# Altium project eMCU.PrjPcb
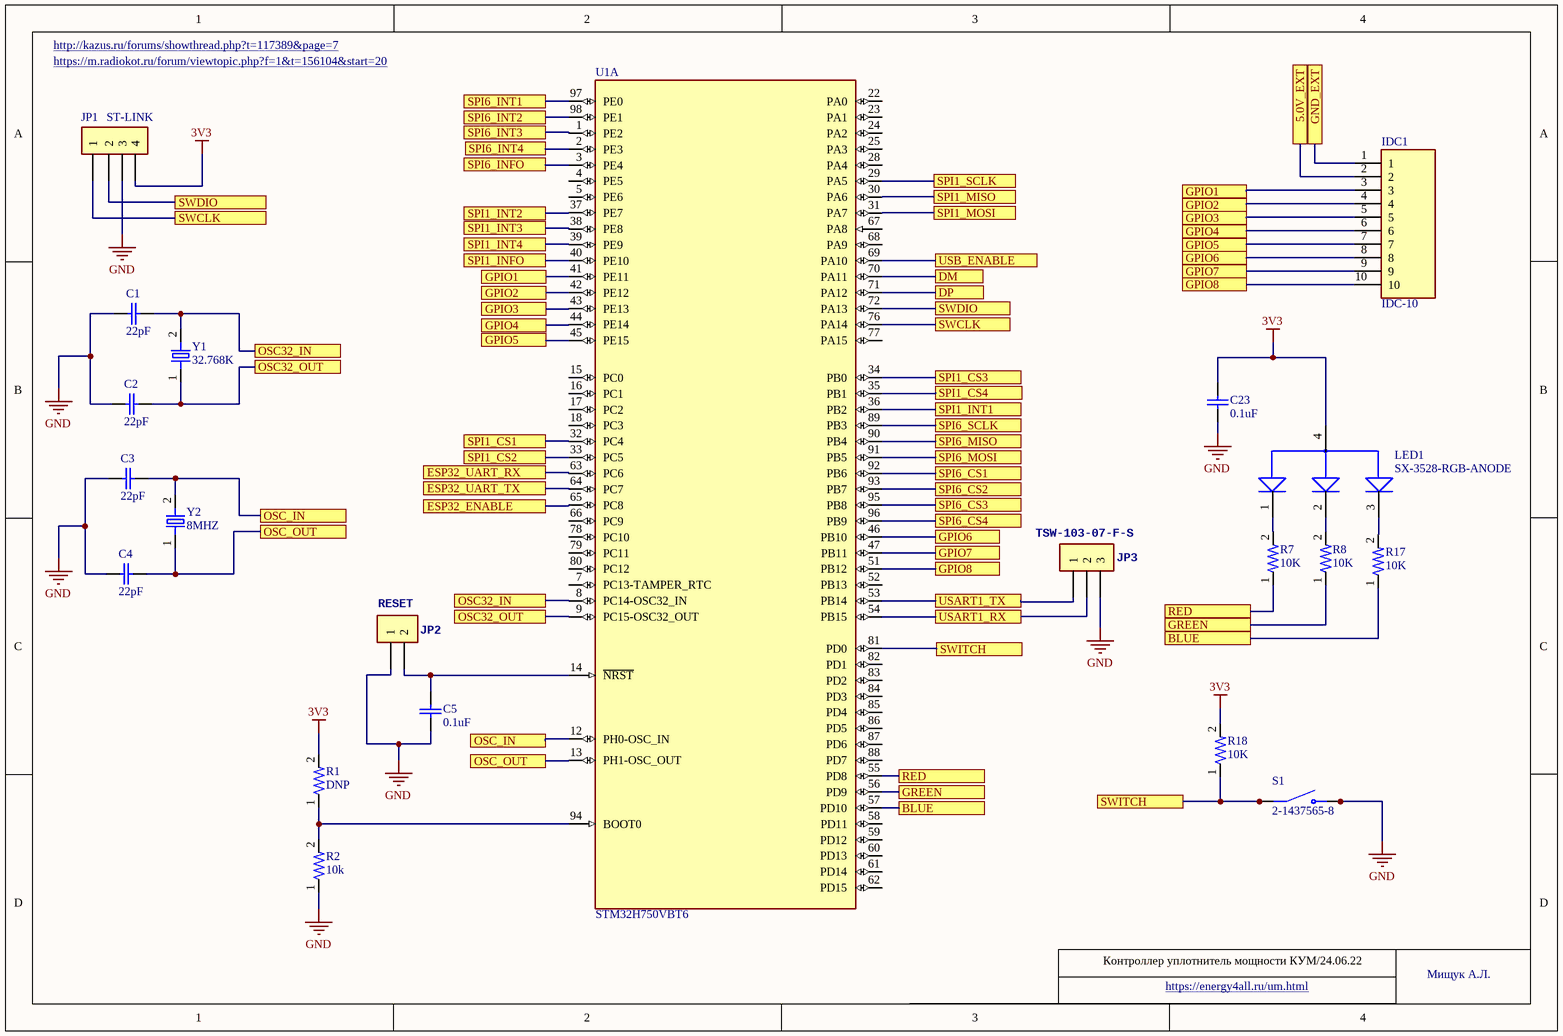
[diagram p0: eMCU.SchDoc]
5 sheets, 66 parts. Net scope: flat (ports and power ports of the same name join across sheets).
Board file: eMCU.PcbDoc
Sheets:
  eMCU.SchDoc
  eSupply.SchDoc
  eUSB.SchDoc
  eWiFi.SchDoc
  eConnect.SchDoc

## Sheet eMCU.SchDoc
size A4; SheetNumber: 1; SheetTotal: 6

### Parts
C1  22pF  [CAP_0603]
C2  22pF  [CAP_0603]
C3  22pF  [CAP_0603]
C4  22pF  [CAP_0603]
C5  0.1uF  [CAP_0603]
C23  0.1uF  [CAP_0603]
IDC1  IDC-10  [IDC-10]
JP1  ST-LINK  [TSW-104-07-F-S]
JP2  RESET  [TSW-102-07-F-S]
JP3  TSW-103-07-F-S  [TSW-103-07-F-S]
LED1  SX-3528-RGB-ANODE  [SX-3528-RGB-ANODE]
R1  DNP  [RESC1608X50N]
R2  10k  [RESC1608X50N]
R7  10K  [RESC1608X50N]
R8  10K  [RESC1608X50N]
R17  10K  [RESC1608X50N]
R18  10K  [RESC1608X50N]
S1  2-1437565-8  [2-1437565-8]
U1  STM32H750VBT6  [STM32H750VBT6]  (part A of 5)
Y1  32.768K  [NX3215SA]
Y2  8MHZ  [NX3225GD]

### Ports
5.0V_EXT, BLUE, DM, DP, ESP32_ENABLE, ESP32_UART_RX, ESP32_UART_TX, GND_EXT, GPIO1, GPIO2, GPIO3, GPIO4, GPIO5, GPIO6, GPIO7, GPIO8, GREEN, OSC32_IN, OSC32_OUT, OSC_IN, OSC_OUT, RED, SPI1_CS1, SPI1_CS2, SPI1_CS3, SPI1_CS4, SPI1_INFO, SPI1_INT1, SPI1_INT2, SPI1_INT3, SPI1_INT4, SPI1_MISO, SPI1_MOSI, SPI1_SCLK, SPI6_CS1, SPI6_CS2, SPI6_CS3, SPI6_CS4, SPI6_INFO, SPI6_INT1, SPI6_INT2, SPI6_INT3, SPI6_INT4, SPI6_MISO, SPI6_MOSI, SPI6_SCLK, SWCLK, SWDIO, SWITCH, USART1_RX, USART1_TX, USB_ENABLE

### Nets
3V3: C23.2 JP1.4 LED1.4(ANODE) R1.2 R18.2
GND: C1.1 C2.1 C3.1 C4.1 C5.1 C23.1 JP1.3 JP2.1 JP3.3 R2.1 S1.3(NO) S1.4(NO)
NetC1_2: C1.2 U1.8(PC14-OSC32_IN) Y1.2 ; port OSC32_IN
NetC2_2: C2.2 U1.9(PC15-OSC32_OUT) Y1.1 ; port OSC32_OUT
NetC3_2: C3.2 U1.12(PH0-OSC_IN) Y2.2 ; port OSC_IN
NetC4_2: C4.2 U1.13(PH1-OSC_OUT) Y2.1 ; port OSC_OUT
NetC5_2: C5.2 JP2.2 U1.14(~{NRST})
NetC21_2: U1.65(PC8) ; port ESP32_ENABLE
NetIDC1_1: IDC1.1 ; port GND_EXT
NetIDC1_2: IDC1.2 ; port 5.0V_EXT
NetIDC1_3: IDC1.3 U1.41(PE11) ; port GPIO1
NetIDC1_4: IDC1.4 U1.42(PE12) ; port GPIO2
NetIDC1_5: IDC1.5 U1.43(PE13) ; port GPIO3
NetIDC1_6: IDC1.6 U1.44(PE14) ; port GPIO4
NetIDC1_7: IDC1.7 U1.45(PE15) ; port GPIO5
NetIDC1_8: IDC1.8 U1.46(PB10) ; port GPIO6
NetIDC1_9: IDC1.9 U1.47(PB11) ; port GPIO7
NetIDC1_10: IDC1.10 U1.51(PB12) ; port GPIO8
NetIDC2_3: U1.89(PB3) ; port SPI6_SCLK
NetIDC2_4: U1.90(PB4) ; port SPI6_MISO
NetIDC2_5: U1.91(PB5) ; port SPI6_MOSI
NetIDC2_6: U1.92(PB6) ; port SPI6_CS1
NetIDC2_7: U1.93(PB7) ; port SPI6_CS2
NetIDC2_8: U1.95(PB8) ; port SPI6_CS3
NetIDC2_9: U1.96(PB9) ; port SPI6_CS4
NetIDC2_10: U1.97(PE0) ; port SPI6_INT1
NetIDC2_11: U1.98(PE1) ; port SPI6_INT2
NetIDC2_12: U1.1(PE2) ; port SPI6_INT3
NetIDC2_13: U1.2(PE3) ; port SPI6_INT4
NetIDC2_14: U1.3(PE4) ; port SPI6_INFO
NetIDC3_3: U1.29(PA5) ; port SPI1_SCLK
NetIDC3_4: U1.30(PA6) ; port SPI1_MISO
NetIDC3_5: U1.31(PA7) ; port SPI1_MOSI
NetIDC3_6: U1.32(PC4) ; port SPI1_CS1
NetIDC3_7: U1.33(PC5) ; port SPI1_CS2
NetIDC3_8: U1.34(PB0) ; port SPI1_CS3
NetIDC3_9: U1.35(PB1) ; port SPI1_CS4
NetIDC3_10: U1.36(PB2) ; port SPI1_INT1
NetIDC3_11: U1.37(PE7) ; port SPI1_INT2
NetIDC3_12: U1.38(PE8) ; port SPI1_INT3
NetIDC3_13: U1.39(PE9) ; port SPI1_INT4
NetIDC3_14: U1.40(PE10) ; port SPI1_INFO
NetJ1_2: U1.70(PA11) ; port DM
NetJ1_3: U1.71(PA12) ; port DP
NetJ3_4: U1.63(PC6) ; port ESP32_UART_RX
NetJ3_5: U1.64(PC7) ; port ESP32_UART_TX
NetJP1_1: JP1.1 U1.76(PA14) ; port SWCLK
NetJP1_2: JP1.2 U1.72(PA13) ; port SWDIO
NetJP3_1: JP3.1 U1.53(PB14) ; port USART1_TX
NetJP3_2: JP3.2 U1.54(PB15) ; port USART1_RX
NetLED1_1: LED1.1(CATHODE_RED) R7.2
NetLED1_2: LED1.2(CATHODE_GREEN) R8.2
NetLED1_3: LED1.3(CATHODE_BLUE) R17.2
NetR1_1: R1.1 R2.2 U1.94(BOOT0)
NetR7_1: R7.1 U1.55(PD8) ; port RED
NetR8_1: R8.1 U1.56(PD9) ; port GREEN
NetR10_2: U1.69(PA10) ; port USB_ENABLE
NetR17_1: R17.1 U1.57(PD10) ; port BLUE
NetR18_1: R18.1 S1.1(COM) S1.2(COM) U1.81(PD0) ; port SWITCH

Not connected (* = marked no-connect by the designer): U1 4(PE5) 5(PE6) 7(PC13-TAMPER_RTC) 15(PC0) 16(PC1) 17(PC2) 18(PC3) 22(PA0) 23(PA1) 24(PA2) 25(PA3) 28(PA4) 52(PB13) 58(PD11) 59(PD12) 60(PD13) 61(PD14) 62(PD15) 66(PC9) 67(PA8) 68(PA9) 77(PA15) 78(PC10) 79(PC11) 80(PC12) 82(PD1) 83(PD2) 84(PD3) 85(PD4) 86(PD5) 87(PD6) 88(PD7)

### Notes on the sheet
- http://kazus.ru/forums/showthread.php?t=117389&page=7
- https://m.radiokot.ru/forum/viewtopic.php?f=1&t=156104&start=20

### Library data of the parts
C1-C5 C23 = CAP_0603
IDC1 = IDC-10: Header, Pin, Idc, Amp-Latch, 10 Pos, Low Profile, Pcb, Vertical, Blue; MF: TE Connectivity; MP: 2-1761603-3; Centerline_Pitch: 2.54 mm[.1 in]; Product_Type: Connector; Number_of_Positions: 10
JP1 = TSW-104-07-F-S: Connector Header Through Hole 4 position 0.100 (2.54mm); MP: TSW-104-24-G-S; MF: Samtec
JP2 = TSW-102-07-F-S
LED1 = SX-3528-RGB-ANODE: LED; SMD 3528, PLCC2; RGB; 3.5x2.8mm; 120Â°; RGB;   3.2-3.6V; MF: Lucky Light; MP: LL-R3528RGBC-008-B
R1 R2 R7 R8 R17 R18 = RES_0603: 1% 0.1W; MP: 1-2176071-4
U1 = STM32H750VBT6: ARM Cortex-M7 STM32H7 Microcontroller IC 32-Bit 480MHz 128KB _128K x 8_ FLASH 100-LQFP _14x14_; MF: STMicroelectronics
Y1 = NX3215SA-32.768K-STD-MUA-8: 32.768 kHz Â±20ppm Crystal 12.5pF 70 kOhms 2-SMD, No Lead; MF: NDK America,
Y2 = NX3225GD: 8MHz Â±20ppm Crystal 18pF 140 Ohms 2-SMD, No Lead; MP: ABM3-8.000MHZ-D2Y-T; MF: Abracon

## Sheet eSupply.SchDoc
size A4; SheetNumber: 2; SheetTotal: 6
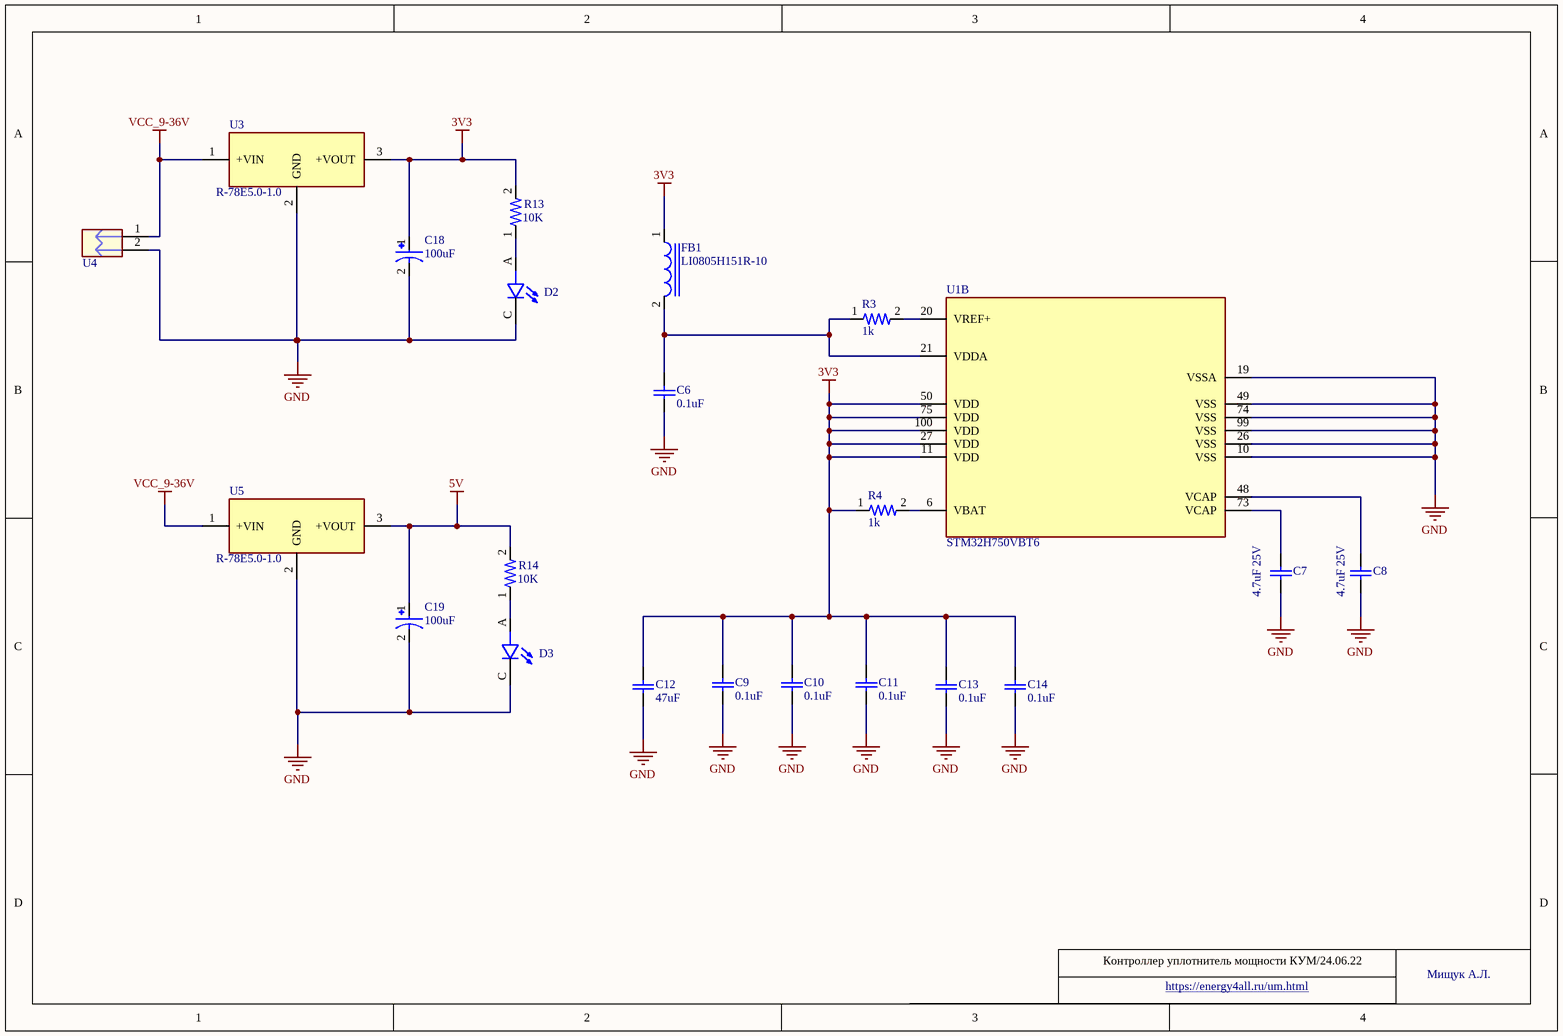
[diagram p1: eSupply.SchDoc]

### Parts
C6  0.1uF  [CAP_0603]
C7  4.7uF 25V  [CAP_0603]
C8  4.7uF 25V  [CAP_0603]
C9  0.1uF  [CAP_0603]
C10  0.1uF  [CAP_0603]
C11  0.1uF  [CAP_0603]
C12  47uF  [CAP_1210]
C13  0.1uF  [CAP_0603]
C14  0.1uF  [CAP_0603]
C18  100uF  [CAP_TYPE_D]
C19  100uF  [CAP_TYPE_D]
D2  led_0603  [led_0603]  (value not drawn)
D3  led_0603  [led_0603]  (value not drawn)
FB1  LI0805H151R-10  [LI0805H151R-10]
R3  1k  [RESC1608X50N]
R4  1k  [RESC1608X50N]
R13  10K  [RESC1608X50N]
R14  10K  [RESC1608X50N]
U1  STM32H750VBT6  [STM32H750VBT6]  (part B of 5)
U3  R-78E5.0-1.0  [R-78E5.0-1.0]
U4  DG129-5.0-02P  [DG129-5.0-02P]  (value not drawn)
U5  R-78E5.0-1.0  [R-78E5.0-1.0]

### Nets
3V3: C9.2 C10.2 C11.2 C12.2 C13.2 C14.2 C18.1 FB1.1 R4.1 R13.2 U1.11(VDD) U1.27(VDD) U1.50(VDD) U1.75(VDD) U1.100(VDD) U3.3(+VOUT)
5V: C19.1 R14.2 U5.3(+VOUT)
GND: C6.1 C7.1 C8.1 C9.1 C10.1 C11.1 C12.1 C13.1 C14.1 C18.2 C19.2 D2.C D3.C U1.10(VSS) U1.19(VSSA) U1.26(VSS) U1.49(VSS) U1.74(VSS) U1.99(VSS) U3.2(GND) U4.2 U5.2(GND)
VCC_9-36V: U3.1(+VIN) U4.1 U5.1(+VIN)
NetC6_2: C6.2 FB1.2 R3.1 U1.21(VDDA)
NetC7_2: C7.2 U1.73(VCAP)
NetC8_2: C8.2 U1.48(VCAP)
NetD2_A: D2.A R13.1
NetD3_A: D3.A R14.1
NetR3_2: R3.2 U1.20(VREF+)
NetR4_2: R4.2 U1.6(VBAT)

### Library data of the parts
C6-C11 C13 C14 = CAP_0603
C12 = CAP_1210
C18 C19 = CAP_TYPE_D: MP: 25TQC15MV
D2 D3 = led_0603: LED Indication - Discrete 3.1V 0603 _1608 Metric_; MP: LTW-C191TLA; MF: Lite-On
FB1 = LI0805H151R-10: 150 Ohms @ 100MHz 1 Power, Signal Line Ferrite Bead 0805 (2012 Metric) 800mA 150mOhm; MF: Laird-Signal Integrity
R3 R4 R13 R14 = RES_0603: 1% 0.1W; MP: 1-2176071-4
U1 = STM32H750VBT6: as U1 on sheet eMCU
U3 U5 = R-78E5.0-1.0: 1A DC/DC-Converter SIP3; MF: Recom Power
U4 = DG129-5.0-02P: DG129-5.0-02P-14-00A(H)

## Sheet eUSB.SchDoc
size A4; SheetNumber: 3; SheetTotal: 6
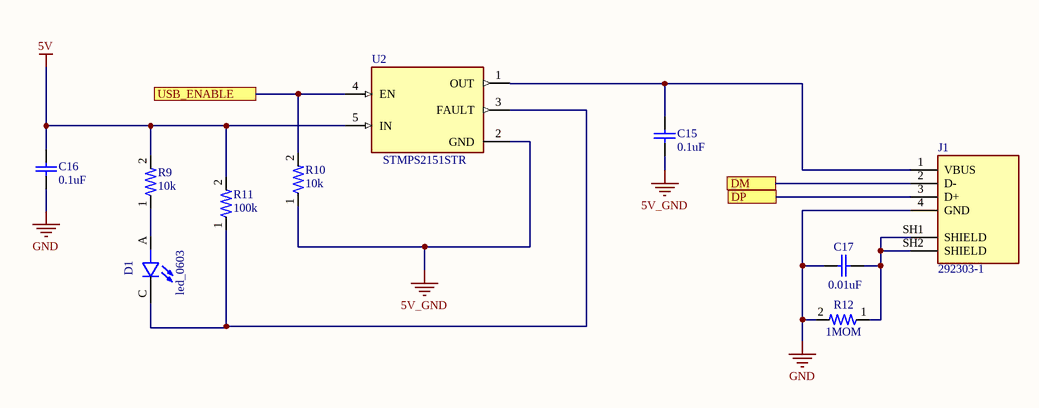
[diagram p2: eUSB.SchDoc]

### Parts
C15  0.1uF  [CAP_0603]
C16  0.1uF  [CAP_0603]
C17  0.01uF  [CAP_0603]
D1  led_0603  [led_0603]
J1  292303-1  [TE_292303-1]
R9  10k  [RESC1608X50N]
R10  10k  [RESC1608X50N]
R11  100k  [RESC1608X50N]
R12  1MOM  [RESC1608X50N]
U2  STMPS2151STR  [STMPS2151STR]

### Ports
DM, DP, USB_ENABLE

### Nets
5V: C16.1 R9.2 R11.2 U2.5(IN)
5V_GND: C15.2 R10.1 U2.2(GND)
GND: C16.2 C17.1 J1.4(GND) R12.2
NetC15_1: C15.1 J1.1(VBUS) U2.1(OUT)
NetC17_2: C17.2 J1.SH1(SHIELD) J1.SH2(SHIELD) R12.1
NetD1_A: D1.A R9.1
NetD1_C: D1.C R11.1 U2.3(FAULT)
NetJ1_2: J1.2(D-) ; port DM
NetJ1_3: J1.3(D+) ; port DP
NetR10_2: R10.2 U2.4(EN) ; port USB_ENABLE

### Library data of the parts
C15-C17 = CAP_0603
D1 = led_0603: as D2 on sheet eSupply
J1 = 292303-1: Conn; Data; USB; Recept; 2.0; 4 Pos; 1 Port; Rt Angle; A Ser; Tin over Copper; Number_of_Positions: 4; Centerline_Pitch: 2 mm[.078 in]; MF: TE Connectivity; Product_Type: Connector
R9-R12 = RES_0603: 1% 0.1W; MP: 1-2176071-4
U2 = STMPS2141STR: Power Switch/Driver 1:1 N-Channel 500mA SOT-23-5; MF: STMicroelectronics

## Sheet eWiFi.SchDoc
size A4; SheetNumber: 4; SheetTotal: 5
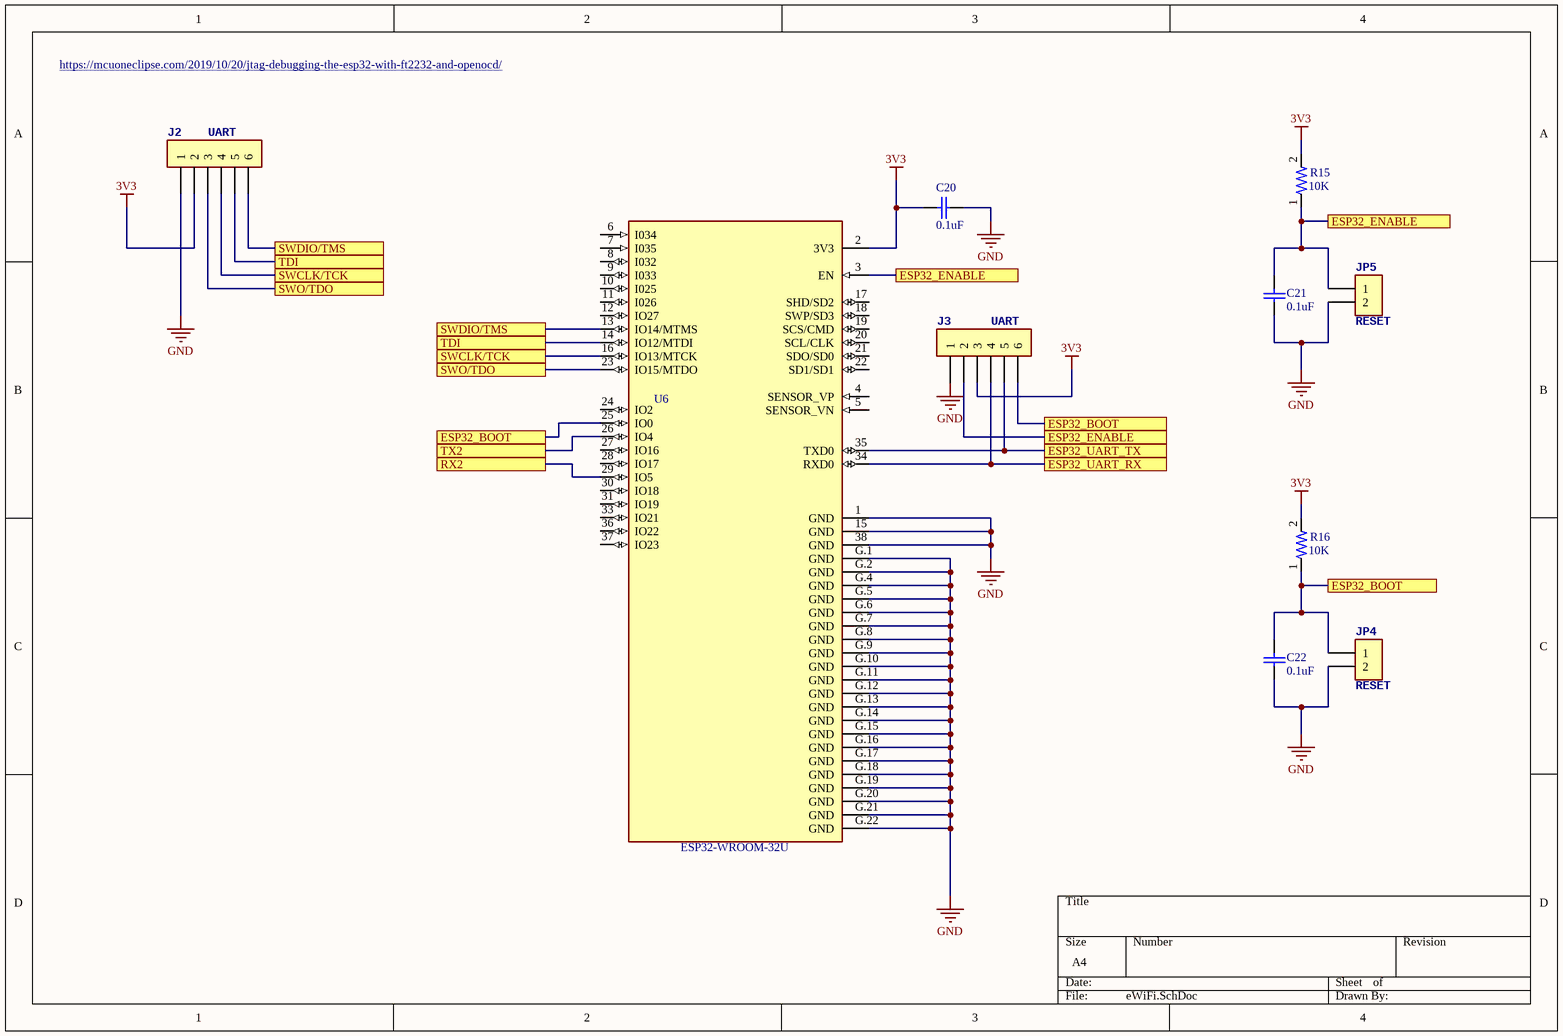
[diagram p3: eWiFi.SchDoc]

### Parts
C20  0.1uF  [CAP_0603]
C21  0.1uF  [CAP_0603]
C22  0.1uF  [CAP_0603]
J2  UART  [TSW-106-07-F-S]
J3  UART  [TSW-106-07-F-S]
JP4  RESET  [TSW-102-07-F-S]
JP5  RESET  [TSW-102-07-F-S]
R15  10K  [RESC1608X50N]
R16  10K  [RESC1608X50N]
U6  ESP32-WROOM-32U  [ESP32-WROOM-32U]

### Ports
ESP32_BOOT, ESP32_ENABLE, ESP32_UART_RX, ESP32_UART_TX, RX2, SWCLK/TCK, SWDIO/TMS, SWO/TDO, TDI, TX2

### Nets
3V3: C20.2 J2.2 J3.3 R15.2 R16.2 U6.2(3V3)
GND: C20.1 C21.1 C22.1 J2.1 J3.1 JP4.2 JP5.2 U6.1(GND) U6.15(GND) U6.38(GND) U6.G.1(GND) U6.G.2(GND) U6.G.4(GND) U6.G.5(GND) U6.G.6(GND) U6.G.7(GND) U6.G.8(GND) U6.G.9(GND) U6.G.10(GND) U6.G.11(GND) U6.G.12(GND) U6.G.13(GND) U6.G.14(GND) U6.G.15(GND) U6.G.16(GND) U6.G.17(GND) U6.G.18(GND) U6.G.19(GND) U6.G.20(GND) U6.G.21(GND) U6.G.22(GND)
NetC21_2: C21.2 J3.2 JP5.1 R15.1 U6.3(EN) ; port ESP32_ENABLE
NetC22_2: C22.2 J3.6 JP4.1 R16.1 U6.25(IO0) ; port ESP32_BOOT
NetJ2_3: J2.3 U6.23(IO15/MTDO) ; port SWO/TDO
NetJ2_4: J2.4 U6.16(IO13/MTCK) ; port SWCLK/TCK
NetJ2_5: J2.5 U6.14(IO12/MTDI) ; port TDI
NetJ2_6: J2.6 U6.13(IO14/MTMS) ; port SWDIO/TMS
NetJ3_4: J3.4 U6.34(RXD0) ; port ESP32_UART_RX
NetJ3_5: J3.5 U6.35(TXD0) ; port ESP32_UART_TX
NetU6_26: U6.26(IO4) ; port TX2
NetU6_29: U6.29(IO5) ; port RX2

Not connected (* = marked no-connect by the designer): U6 4(SENSOR_VP) 5(SENSOR_VN) 6(I034) 7(I035) 8(I032) 9(I033) 10(I025) 11(I026) 12(IO27) 17(SHD/SD2) 18(SWP/SD3) 19(SCS/CMD) 20(SCL/CLK) 21(SDO/SD0) 22(SD1/SD1) 24(IO2) 27(IO16) 28(IO17) 30(IO18) 31(IO19) 33(IO21) 36(IO22) 37(IO23)

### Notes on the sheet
- https://mcuoneclipse.com/2019/10/20/jtag-debugging-the-esp32-with-ft2232-and-openocd/

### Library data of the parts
C20-C22 = CAP_0603
J2 J3 = TSW-106-07-F-S
JP4 JP5 = TSW-102-07-F-S
R15 R16 = RES_0603: 1% 0.1W; MP: 1-2176071-4
U6 = ESP32-WROOM-32U: Bluetooth, WiFi 802.11b/g/n, Bluetooth v4.2 +EDR, Class 1, 2 and 3 Transceiver Module 2.4GHz ~ 2.5GHz Antenna Not Included, U.FL Surface Mount; MF: Espressif Systems

## Sheet eConnect.SchDoc
size A4; SheetNumber: 5; SheetTotal: 6
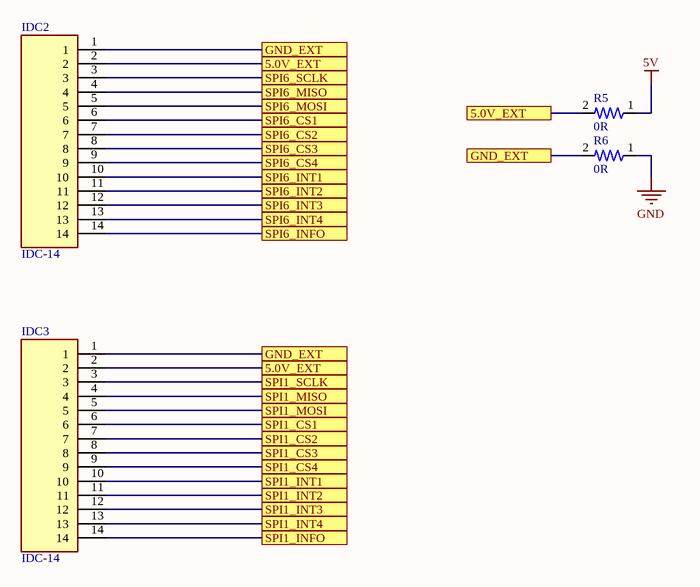
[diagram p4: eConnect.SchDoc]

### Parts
IDC2  IDC-14  [IDC-14]
IDC3  IDC-14  [IDC-14]
R5  0R  [RESC1608X50N]
R6  0R  [RESC1608X50N]

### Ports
5.0V_EXT, GND_EXT, SPI1_CS1, SPI1_CS2, SPI1_CS3, SPI1_CS4, SPI1_INFO, SPI1_INT1, SPI1_INT2, SPI1_INT3, SPI1_INT4, SPI1_MISO, SPI1_MOSI, SPI1_SCLK, SPI6_CS1, SPI6_CS2, SPI6_CS3, SPI6_CS4, SPI6_INFO, SPI6_INT1, SPI6_INT2, SPI6_INT3, SPI6_INT4, SPI6_MISO, SPI6_MOSI, SPI6_SCLK

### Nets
5V: R5.1
GND: R6.1
NetIDC1_1: IDC2.1 IDC3.1 R6.2 ; port GND_EXT
NetIDC1_2: IDC2.2 IDC3.2 R5.2 ; port 5.0V_EXT
NetIDC2_3: IDC2.3 ; port SPI6_SCLK
NetIDC2_4: IDC2.4 ; port SPI6_MISO
NetIDC2_5: IDC2.5 ; port SPI6_MOSI
NetIDC2_6: IDC2.6 ; port SPI6_CS1
NetIDC2_7: IDC2.7 ; port SPI6_CS2
NetIDC2_8: IDC2.8 ; port SPI6_CS3
NetIDC2_9: IDC2.9 ; port SPI6_CS4
NetIDC2_10: IDC2.10 ; port SPI6_INT1
NetIDC2_11: IDC2.11 ; port SPI6_INT2
NetIDC2_12: IDC2.12 ; port SPI6_INT3
NetIDC2_13: IDC2.13 ; port SPI6_INT4
NetIDC2_14: IDC2.14 ; port SPI6_INFO
NetIDC3_3: IDC3.3 ; port SPI1_SCLK
NetIDC3_4: IDC3.4 ; port SPI1_MISO
NetIDC3_5: IDC3.5 ; port SPI1_MOSI
NetIDC3_6: IDC3.6 ; port SPI1_CS1
NetIDC3_7: IDC3.7 ; port SPI1_CS2
NetIDC3_8: IDC3.8 ; port SPI1_CS3
NetIDC3_9: IDC3.9 ; port SPI1_CS4
NetIDC3_10: IDC3.10 ; port SPI1_INT1
NetIDC3_11: IDC3.11 ; port SPI1_INT2
NetIDC3_12: IDC3.12 ; port SPI1_INT3
NetIDC3_13: IDC3.13 ; port SPI1_INT4
NetIDC3_14: IDC3.14 ; port SPI1_INFO

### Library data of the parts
IDC2 IDC3 = IDC-14: HEADER, PIN, AMP-LATCH, 14 POS, 2.54 X 2.54, VERTICAL, LOW PROFILE, PCB; MP: 5104338-2; Product_Type: Connector; Centerline_Pitch: 2.54 mm[.1 in]; MF: TE Connectivity; Number_of_Positions: 14
R5 R6 = RES_0603: 1% 0.1W; MP: 1-2176071-4

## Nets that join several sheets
3V3: eMCU (5 pins), eSupply (16 pins), eWiFi (6 pins)
5V: eSupply (C19.1 R14.2 U5.3), eUSB (C16.1 R9.2 R11.2 U2.5), eConnect (R5.1)
GND: eMCU (12 pins), eSupply (22 pins), eUSB (C16.2 C17.1 J1.4 R12.2), eWiFi (31 pins), eConnect (R6.1)
NetC21_2: eMCU (U1.65), eWiFi (5 pins)
NetIDC1_1: eMCU (IDC1.1), eConnect (IDC2.1 IDC3.1 R6.2)
NetIDC1_2: eMCU (IDC1.2), eConnect (IDC2.2 IDC3.2 R5.2)
NetIDC2_3: eMCU (U1.89), eConnect (IDC2.3)
NetIDC2_4: eMCU (U1.90), eConnect (IDC2.4)
NetIDC2_5: eMCU (U1.91), eConnect (IDC2.5)
NetIDC2_6: eMCU (U1.92), eConnect (IDC2.6)
NetIDC2_7: eMCU (U1.93), eConnect (IDC2.7)
NetIDC2_8: eMCU (U1.95), eConnect (IDC2.8)
NetIDC2_9: eMCU (U1.96), eConnect (IDC2.9)
NetIDC2_10: eMCU (U1.97), eConnect (IDC2.10)
NetIDC2_11: eMCU (U1.98), eConnect (IDC2.11)
NetIDC2_12: eMCU (U1.1), eConnect (IDC2.12)
NetIDC2_13: eMCU (U1.2), eConnect (IDC2.13)
NetIDC2_14: eMCU (U1.3), eConnect (IDC2.14)
NetIDC3_3: eMCU (U1.29), eConnect (IDC3.3)
NetIDC3_4: eMCU (U1.30), eConnect (IDC3.4)
NetIDC3_5: eMCU (U1.31), eConnect (IDC3.5)
NetIDC3_6: eMCU (U1.32), eConnect (IDC3.6)
NetIDC3_7: eMCU (U1.33), eConnect (IDC3.7)
NetIDC3_8: eMCU (U1.34), eConnect (IDC3.8)
NetIDC3_9: eMCU (U1.35), eConnect (IDC3.9)
NetIDC3_10: eMCU (U1.36), eConnect (IDC3.10)
NetIDC3_11: eMCU (U1.37), eConnect (IDC3.11)
NetIDC3_12: eMCU (U1.38), eConnect (IDC3.12)
NetIDC3_13: eMCU (U1.39), eConnect (IDC3.13)
NetIDC3_14: eMCU (U1.40), eConnect (IDC3.14)
NetJ1_2: eMCU (U1.70), eUSB (J1.2)
NetJ1_3: eMCU (U1.71), eUSB (J1.3)
NetJ3_4: eMCU (U1.63), eWiFi (J3.4 U6.34)
NetJ3_5: eMCU (U1.64), eWiFi (J3.5 U6.35)
NetR10_2: eMCU (U1.69), eUSB (R10.2 U2.4)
